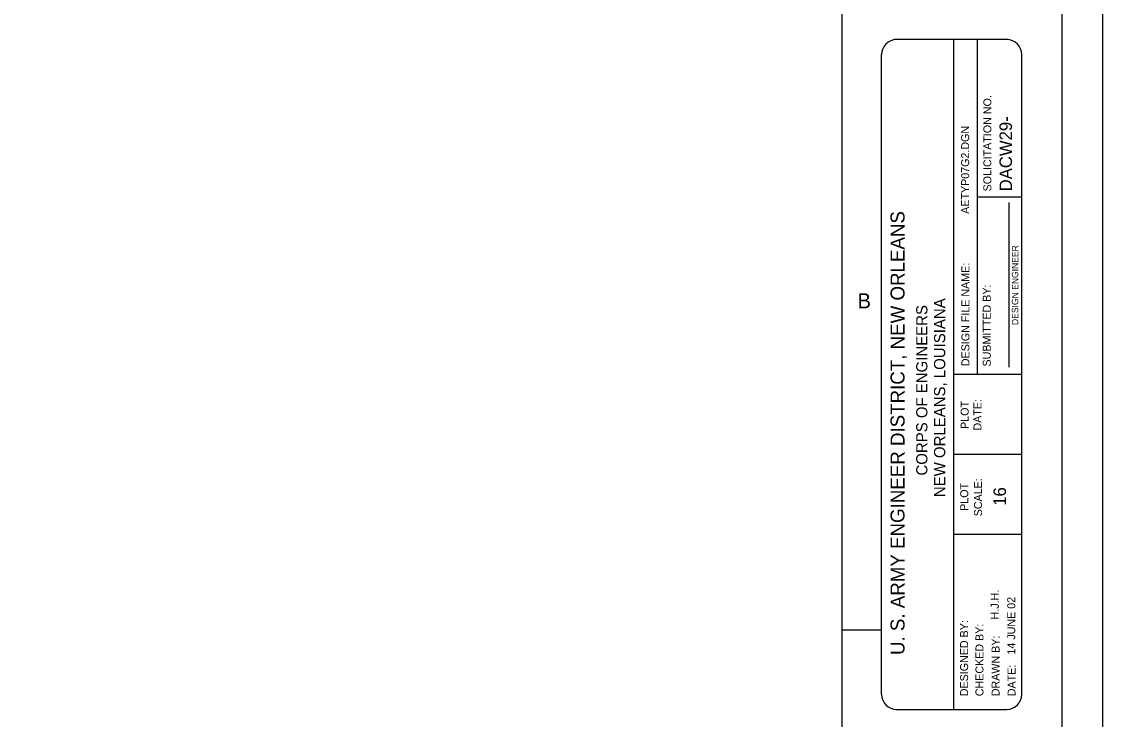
# Model space of a CAD drawing. Extents: x 22339.2 to 22413.4, y 22369.6 to 22418.8.
# Drawn here: x 22395.37 to 22413.39, y 22379.79 to 22391.43 of the extents above; entities that cross this region are included whole.
import ezdxf

# ---------------------------------------------------------------- set-up
doc = ezdxf.new("R2010")
doc.units = 0
for name, color, linetype in [('Level 1', 7, 'Continuous'), ('Level 10', 7, 'Continuous'), ('Level 2', 7, 'Continuous'), ('Level 7', 7, 'Continuous'), ('Level 9', 7, 'Continuous')]:
    doc.layers.add(name, color=color, linetype=linetype)

msp = doc.modelspace()

# ---------------------------------------------------------------- linework, layer by layer
at = {"layer": 'Level 1'}
for p, q in [((22411.818, 22391.125), (22409.914, 22391.125)), ((22410.906, 22391.125), (22410.906, 22379.957))]:
    msp.add_line(p, q, dxfattribs=at)
msp.add_lwpolyline([(22354.719, 22414.965), (22413.386, 22414.965), (22413.386, 22369.621), (22354.719, 22369.621)], close=True, dxfattribs=at)
for points in [[(22411.792, 22391.125), (22409.956, 22391.125)], [(22409.706, 22380.207), (22409.706, 22390.875)], [(22412.042, 22380.207), (22412.042, 22390.875)], [(22409.956, 22379.957), (22411.792, 22379.957)]]:
    msp.add_lwpolyline(points, dxfattribs=at)
for centre, start, end in [((22409.956, 22390.875), 90, 180), ((22411.792, 22390.875), 0, 90), ((22409.956, 22380.207), 180, 270), ((22411.792, 22380.207), 270, 0)]:
    msp.add_arc(centre, 0.25, start, end, dxfattribs=at)
at = {"layer": 'Level 10'}
msp.add_line((22409.05, 22381.285), (22409.706, 22381.285), dxfattribs=at)
at = {"layer": 'Level 2'}
for p, q in [((22411.299, 22391.125), (22411.299, 22385.541)), ((22412.042, 22388.496), (22411.299, 22388.496)), ((22411.834, 22385.662), (22411.834, 22388.411)), ((22412.042, 22385.541), (22410.906, 22385.541)), ((22412.042, 22384.208), (22410.906, 22384.208)), ((22412.042, 22382.875), (22410.906, 22382.875))]:
    msp.add_line(p, q, dxfattribs=at)
at = {"layer": 'Level 9'}
msp.add_line((22412.714, 22370.293), (22412.714, 22414.293), dxfattribs=at)
msp.add_lwpolyline([(22409.05, 22370.293), (22409.05, 22414.293)], dxfattribs=at)

# ---------------------------------------------------------------- texts
at = {"layer": 'Level 1'}
for s, height, p in [('SOLICITATION NO.', 0.13334, (22411.536, 22388.594)), ('AETYP07G2.DGN', 0.13334, (22411.166, 22388.22)), ('U. S. ARMY ENGINEER DISTRICT, NEW ORLEANS', 0.23333, (22410.089, 22380.863)), ('DESIGN ENGINEER', 0.10665, (22411.984, 22386.366)), ('DESIGN FILE NAME:', 0.13334, (22411.17, 22385.68)), ('SUBMITTED BY:', 0.13334, (22411.526, 22385.674)), ('PLOT', 0.1333, (22411.158, 22384.633)), ('DATE:', 0.1333, (22411.371, 22384.606)), ('SCALE:', 0.1333, (22411.38, 22383.176)), ('PLOT', 0.1333, (22411.151, 22383.267)), ('H.J.H.', 0.1333, (22411.66, 22381.457)), ('14 JUNE 02', 0.1333, (22411.934, 22380.871)), ('DESIGNED BY:', 0.13334, (22411.148, 22380.176)), ('CHECKED BY:', 0.13334, (22411.404, 22380.176)), ('DRAWN BY:', 0.1333, (22411.673, 22380.176)), ('DATE:', 0.1333, (22411.939, 22380.176))]:
    msp.add_text(s, height=height, rotation=90, dxfattribs=at).set_placement(p)
msp.add_text('B', height=0.25, dxfattribs=at).set_placement((22409.306, 22386.645))
at = {"layer": 'Level 7'}
for s, height, p in [('DACW29-', 0.208, (22411.88, 22388.595)), ('NEW ORLEANS, LOUISIANA', 0.18667, (22410.767, 22383.496)), ('CORPS OF ENGINEERS', 0.18667, (22410.47, 22383.856)), ('16', 0.208, (22411.779, 22383.352))]:
    msp.add_text(s, height=height, rotation=90, dxfattribs=at).set_placement(p)

doc.saveas('drawing.dxf')
